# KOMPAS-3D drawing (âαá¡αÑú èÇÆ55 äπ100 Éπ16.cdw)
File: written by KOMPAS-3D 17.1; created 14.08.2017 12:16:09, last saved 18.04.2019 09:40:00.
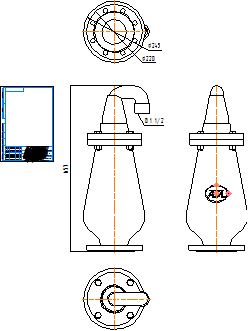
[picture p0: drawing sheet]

Sheet 1: A4, portrait

Title block, sheet 1: name: Гранрег КАТ55 Ду100 Ру16; material: Внимание! Данный продукт является объектом авторского права ООО «Торговый Дом АДЛ». / Запрещается изменение, копирование, распространение / (в том числе путем копирования на другие сайты и ресурсы в Интернете) / или любое иное использование информации и объектов без предварительного / согласия правообладателя (ООО «Торговый Дом АДЛ»).; mass: 116,3; sheets: 1; organisation: ООО "Торговый дом АДЛ"; sheet format: A4; stored path: \\adlc.lan\data\АДЛ_ПКД\3D-модели\ADL production\Клапаны КАТ ГРАНРЕГ\КАТ55\KOMPAS 2D\Гранрег КАТ55 Ду100 Ру16.cdw

Views: Вид 1, Проекционный вид 2, Проекционный вид 3, Проекционный вид 4, Проекционный вид 5
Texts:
  kka
  adl
Dimensions and other numbers on the sheet: 657; 245; 220; 1:1; 1; 116,3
